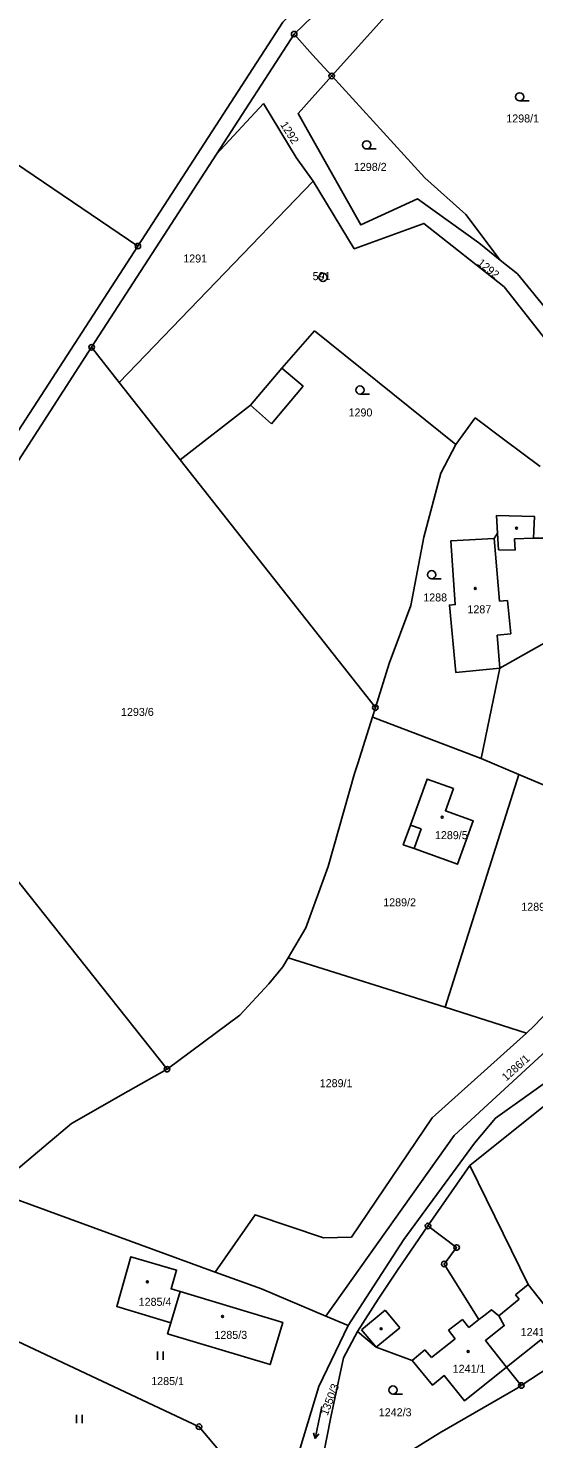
# Model space of a CAD drawing. Extents: x -587171 to -555306, y -1167727 to -1074732.
# Drawn here: x -559945 to -559852.9, y -1076722.9 to -1076465.6 of the extents above; entities that cross this region are included whole.
import ezdxf

# ---------------------------------------------------------------- set-up
doc = ezdxf.new("R2010")
doc.units = 0
for name, color, linetype in [('Hranice parcel', 7, 'Continuous'), ('Parcelní čísla', 7, 'Continuous'), ('Vnitřní kresba', 7, 'Continuous'), ('Značky bodu BP', 7, 'Continuous'), ('Značky budov', 7, 'Continuous'), ('Značky kultur', 7, 'Continuous')]:
    doc.layers.add(name, color=color, linetype=linetype)

msp = doc.modelspace()

# ---------------------------------------------------------------- linework, layer by layer
at = {"layer": 'Hranice parcel'}
for p, q in [((-559889.72, -1076474.32), (-559862.58, -1076444)), ((-559996.59, -1076456.83), (-559925.05, -1076505.35)), ((-559891.57, -1076461.9), (-559896.56, -1076466.69)), ((-559896.56, -1076466.69), (-559910.72, -1076488.59)), ((-559902.17, -1076479.35), (-559910.72, -1076488.59)), ((-559910.72, -1076488.59), (-559933.49, -1076523.8)), ((-559893.11, -1076493.49), (-559928.45, -1076530.21)), ((-559925.05, -1076505.35), (-559948.16, -1076541.06)), ((-559974.24, -1076586.81), (-559933.49, -1076523.8)), ((-559933.49, -1076523.8), (-559928.45, -1076530.21)), ((-559859.08, -1076582.34), (-559849.04, -1076576.7)), ((-559862.46, -1076598.83), (-559859.08, -1076582.34)), ((-559974.24, -1076586.81), (-559919.74, -1076655.48)), ((-559881.76, -1076589.52), (-559882.3, -1076591.23)), ((-559855.62, -1076601.74), (-559862.46, -1076598.83)), ((-559869.04, -1076644.18), (-559855.62, -1076601.74)), ((-559837.97, -1076609.15), (-559855.62, -1076601.74)), ((-559869.04, -1076644.18), (-559897.63, -1076635.14)), ((-559854.21, -1076648.87), (-559869.04, -1076644.18)), ((-559871.37, -1076664.34), (-559854.21, -1076648.87)), ((-559864.54, -1076673.01), (-559872.16, -1076684.06)), ((-559910.99, -1076692.46), (-559948.65, -1076678.67)), ((-559917.37, -1076696.03), (-559919.06, -1076701.73)), ((-559886.72, -1076702.24), (-559890.81, -1076700.51)), ((-559857.82, -1076709.81), (-559855.15, -1076713.16))]:
    msp.add_line(p, q, dxfattribs=at)
for points in [[(-559895.99, -1076461.99), (-559898.64, -1076464.53), (-559925.05, -1076505.35)], [(-559889.72, -1076474.32), (-559893.2, -1076470.44), (-559896.56, -1076466.69)], [(-559858.98, -1076507.89), (-559862.91, -1076504.75), (-559874.05, -1076496.75), (-559884.41, -1076501.49), (-559893.61, -1076485.19), (-559895.86, -1076481.17), (-559889.72, -1076474.32)], [(-559889.72, -1076474.32), (-559872.75, -1076492.89), (-559865.24, -1076499.58), (-559858.98, -1076507.89)], [(-559893.11, -1076493.49), (-559896.18, -1076489.21), (-559902.17, -1076479.35)], [(-559845.09, -1076529.56), (-559858.29, -1076512.76), (-559872.94, -1076501.21), (-559885.6, -1076505.83), (-559893.11, -1076493.49)], [(-559843.46, -1076525.61), (-559855.81, -1076510.42), (-559858.98, -1076507.89)], [(-559928.45, -1076530.21), (-559917.32, -1076544.34), (-559881.76, -1076589.52)], [(-559851.71, -1076545.53), (-559858.37, -1076540.59), (-559863.55, -1076536.7), (-559867.09, -1076541.55), (-559869.82, -1076546.77), (-559872.92, -1076558.44), (-559875.26, -1076570.87), (-559879.21, -1076581.46), (-559881.76, -1076589.52)], [(-559848.34, -1076558.74), (-559848.97, -1076558.64), (-559851.55, -1076558.63), (-559852.9, -1076558.64), (-559852.76, -1076554.66), (-559859.66, -1076554.48), (-559859.46, -1076557.69), (-559860.07, -1076558.69), (-559867.98, -1076559.1), (-559867.2, -1076570.73), (-559868.26, -1076570.83), (-559867.07, -1076583.14), (-559859.08, -1076582.34)], [(-559897.63, -1076635.14), (-559894.45, -1076629.67), (-559890.38, -1076618.52), (-559885.54, -1076601.52), (-559884.98, -1076599.74), (-559882.3, -1076591.23)], [(-559882.3, -1076591.23), (-559881.8, -1076591.42), (-559862.46, -1076598.83)], [(-559886.72, -1076702.24), (-559876.58, -1076686.53), (-559863.65, -1076668.94), (-559859.88, -1076664.4), (-559841.42, -1076651.26), (-559836.65, -1076644.06), (-559833.46, -1076627.56), (-559832.51, -1076620.32), (-559830.89, -1076610.06), (-559828.66, -1076600.86)], [(-559875.37, -1076610.94), (-559872.33, -1076602.56), (-559867.53, -1076604.3), (-559868.97, -1076608.34), (-559863.92, -1076610.18), (-559866.76, -1076618.1), (-559874.69, -1076615.24), (-559876.67, -1076614.52), (-559875.37, -1076610.94)], [(-559890.81, -1076700.51), (-559867.4, -1076667.56), (-559838.3, -1076640.75), (-559833.93, -1076609.06)], [(-559854.21, -1076648.87), (-559852.71, -1076647.52), (-559843.31, -1076637.61), (-559837.97, -1076609.15)], [(-559919.74, -1076655.48), (-559906.48, -1076645.63), (-559901.17, -1076639.9), (-559898.6, -1076636.81), (-559897.63, -1076635.14)], [(-559949.18, -1076675.5), (-559937.16, -1076665.37), (-559926.85, -1076659.45), (-559919.74, -1076655.48)], [(-559849.14, -1076660.77), (-559850.79, -1076662.01), (-559864.54, -1076673.01)], [(-559910.99, -1076692.46), (-559903.7, -1076682.01), (-559891.22, -1076686.21), (-559886.12, -1076686.1), (-559871.37, -1076664.34)], [(-559857.82, -1076709.81), (-559851.57, -1076704.83), (-559850.74, -1076705.83), (-559847.3, -1076703.1), (-559853.88, -1076694.72), (-559864.54, -1076673.01)], [(-559855.15, -1076713.16), (-559844.62, -1076706.22), (-559840.22, -1076701.79), (-559835.14, -1076695.29), (-559826.06, -1076680.68)], [(-559872.16, -1076684.06), (-559877.73, -1076692.14), (-559881.24, -1076697.44), (-559885.03, -1076703.32)], [(-559861.95, -1076700.43), (-559862.87, -1076701.14), (-559869.2, -1076691.01), (-559866.94, -1076688), (-559872.16, -1076684.06)], [(-559919.06, -1076701.73), (-559928.92, -1076698.77), (-559926.31, -1076689.69), (-559918, -1076692.12), (-559919, -1076695.52), (-559917.37, -1076696.03)], [(-559890.81, -1076700.51), (-559902.52, -1076695.56), (-559910.99, -1076692.46)], [(-559917.37, -1076696.03), (-559898.64, -1076701.65), (-559900.92, -1076709.36), (-559919.65, -1076703.73), (-559919.06, -1076701.73)], [(-559958.09, -1076699.95), (-559954.36, -1076701.7), (-559913.91, -1076720.68), (-559901.45, -1076735.49)], [(-559859.25, -1076700.46), (-559860.56, -1076699.35), (-559861.95, -1076700.43)], [(-559857.82, -1076709.81), (-559861.69, -1076704.97), (-559858.25, -1076702.22), (-559859.25, -1076700.46)], [(-559894.79, -1076732.04), (-559895.44, -1076724.62), (-559892.05, -1076713.34), (-559886.72, -1076702.24)], [(-559885.03, -1076703.32), (-559887.56, -1076708.1), (-559889.85, -1076718.91), (-559892, -1076729.76)], [(-559885.03, -1076703.32), (-559881.61, -1076706.18), (-559875.05, -1076708.59), (-559871.36, -1076713.08), (-559869.2, -1076711.35), (-559865.52, -1076715.95), (-559857.82, -1076709.81)], [(-559892, -1076729.76), (-559884.1, -1076729.75), (-559876.58, -1076725.85), (-559869.98, -1076721.78), (-559855.77, -1076713.57), (-559855.15, -1076713.16)]]:
    msp.add_lwpolyline(points, dxfattribs=at)
at = {"layer": 'Vnitřní kresba'}
for p, q in [((-559892.85, -1076520.81), (-559898.8, -1076527.59)), ((-559867.09, -1076541.55), (-559892.85, -1076520.81)), ((-559904.5, -1076534.38), (-559898.8, -1076527.59)), ((-559894.94, -1076530.87), (-559898.8, -1076527.59)), ((-559900.7, -1076537.74), (-559894.94, -1076530.87)), ((-559904.5, -1076534.38), (-559917.32, -1076544.34)), ((-559904.5, -1076534.38), (-559900.7, -1076537.74)), ((-559859.11, -1076570.1), (-559860.07, -1076558.69)), ((-559859.46, -1076557.69), (-559859.28, -1076560.73)), ((-559856.39, -1076558.71), (-559852.9, -1076558.64)), ((-559856.27, -1076560.81), (-559856.39, -1076558.71)), ((-559859.28, -1076560.73), (-559856.27, -1076560.81)), ((-559857.66, -1076569.96), (-559859.11, -1076570.1)), ((-559857.05, -1076576.09), (-559857.66, -1076569.96)), ((-559859.56, -1076576.34), (-559857.05, -1076576.09)), ((-559859.08, -1076582.34), (-559859.56, -1076576.34)), ((-559875.37, -1076610.94), (-559873.39, -1076611.65)), ((-559873.39, -1076611.65), (-559874.69, -1076615.24)), ((-559853.88, -1076694.72), (-559856.19, -1076696.62)), ((-559855.53, -1076697.42), (-559859.25, -1076700.46)), ((-559856.19, -1076696.62), (-559855.53, -1076697.42)), ((-559884.3, -1076703.03), (-559879.98, -1076699.44)), ((-559879.98, -1076699.44), (-559877.29, -1076702.62)), ((-559865.89, -1076701.12), (-559868.43, -1076703.09)), ((-559864.74, -1076702.6), (-559865.89, -1076701.12)), ((-559862.87, -1076701.14), (-559864.74, -1076702.6)), ((-559884.3, -1076703.03), (-559881.61, -1076706.18)), ((-559877.29, -1076702.62), (-559881.61, -1076706.18)), ((-559868.43, -1076703.09), (-559867.21, -1076704.65)), ((-559867.21, -1076704.65), (-559871.54, -1076708.03)), ((-559872.72, -1076706.63), (-559875.05, -1076708.59)), ((-559871.54, -1076708.03), (-559872.72, -1076706.63))]:
    msp.add_line(p, q, dxfattribs=at)
at = {"layer": 'Značky bodu BP'}
for centre, radius in [((-559896.56, -1076466.69), 0.5), ((-559896.56, -1076466.69), 0.0303), ((-559889.72, -1076474.32), 0.5), ((-559889.72, -1076474.32), 0.0303), ((-559925.05, -1076505.35), 0.5), ((-559925.05, -1076505.35), 0.0303), ((-559891.3, -1076511.06), 0.75), ((-559891.3, -1076511.06), 0.03), ((-559933.49, -1076523.8), 0.5), ((-559933.49, -1076523.8), 0.0303), ((-559881.76, -1076589.52), 0.5), ((-559881.76, -1076589.52), 0.0303), ((-559919.74, -1076655.48), 0.5), ((-559919.74, -1076655.48), 0.0303), ((-559872.16, -1076684.06), 0.5), ((-559872.16, -1076684.06), 0.0303), ((-559866.94, -1076688), 0.5), ((-559866.94, -1076688), 0.0303), ((-559869.2, -1076691.01), 0.5), ((-559869.2, -1076691.01), 0.0303), ((-559855.15, -1076713.16), 0.5), ((-559855.15, -1076713.16), 0.0303), ((-559913.91, -1076720.68), 0.5), ((-559913.91, -1076720.68), 0.0303)]:
    msp.add_circle(centre, radius, dxfattribs=at)
at = {"layer": 'Značky budov'}
for centre in [(-559856, -1076556.78), (-559863.53, -1076567.78), (-559869.57, -1076609.51), (-559923.33, -1076694.24), (-559909.62, -1076700.56), (-559880.71, -1076702.8), (-559864.83, -1076706.96)]:
    msp.add_circle(centre, 0.175, dxfattribs=at)
at = {"layer": 'Značky kultur'}
for p, q in [((-559855.44, -1076478.87), (-559853.69, -1076478.87)), ((-559883.34, -1076487.64), (-559881.59, -1076487.64)), ((-559884.57, -1076532.35), (-559882.82, -1076532.35)), ((-559871.49, -1076566.04), (-559869.74, -1076566.04)), ((-559921.45, -1076708.45), (-559921.45, -1076706.95)), ((-559920.45, -1076708.45), (-559920.45, -1076706.95)), ((-559878.54, -1076714.74), (-559876.79, -1076714.74)), ((-559936.22, -1076720), (-559936.22, -1076718.5)), ((-559935.22, -1076720), (-559935.22, -1076718.5)), ((-559891.49, -1076716.98), (-559892.74, -1076722.85)), ((-559892.74, -1076722.85), (-559893.02, -1076721.79)), ((-559892.74, -1076722.85), (-559892.04, -1076722))]:
    msp.add_line(p, q, dxfattribs=at)
for centre in [(-559855.44, -1076478.12), (-559883.34, -1076486.89), (-559884.57, -1076531.6), (-559871.49, -1076565.29), (-559878.54, -1076713.99)]:
    msp.add_circle(centre, 0.75, dxfattribs=at)

# ---------------------------------------------------------------- texts
at = {"layer": 'Parcelní čísla'}
for s, rotation, p in [('1292', 302, (-559899.16, -1076483.19)), ('1292', 321, (-559863.28, -1076508.65)), ('1286/1', 42, (-559857.9, -1076657.74)), ('1350/3', 69, (-559890.47, -1076718.75))]:
    msp.add_text(s, height=1.46, rotation=rotation, dxfattribs=at).set_placement(p)
for s, p in [('1298/1', (-559857.88, -1076482.8)), ('1298/2', (-559885.67, -1076491.63)), ('1291', (-559916.78, -1076508.34)), ('1290', (-559886.64, -1076536.42)), ('1288', (-559873.02, -1076570.16)), ('1287', (-559864.97, -1076572.32)), ('1293/6', (-559928.13, -1076591.04)), ('1289/5', (-559870.89, -1076613.51)), ('1289/2', (-559880.32, -1076625.77)), ('1289/3', (-559855.15, -1076626.58)), ('1289/1', (-559891.9, -1076658.75)), ('1285/4', (-559924.91, -1076698.63)), ('1285/3', (-559911.1, -1076704.66)), ('1241/2', (-559855.26, -1076704.14)), ('1285/1', (-559922.62, -1076713.08)), ('1241/1', (-559867.66, -1076710.84)), ('1242/3', (-559881.13, -1076718.77))]:
    msp.add_text(s, height=1.46, dxfattribs=at).set_placement(p)
at = {"layer": 'Značky bodu BP'}
msp.add_text('591', height=1.46, dxfattribs=at).set_placement((-559893.19, -1076511.56))

doc.saveas('drawing.dxf')
